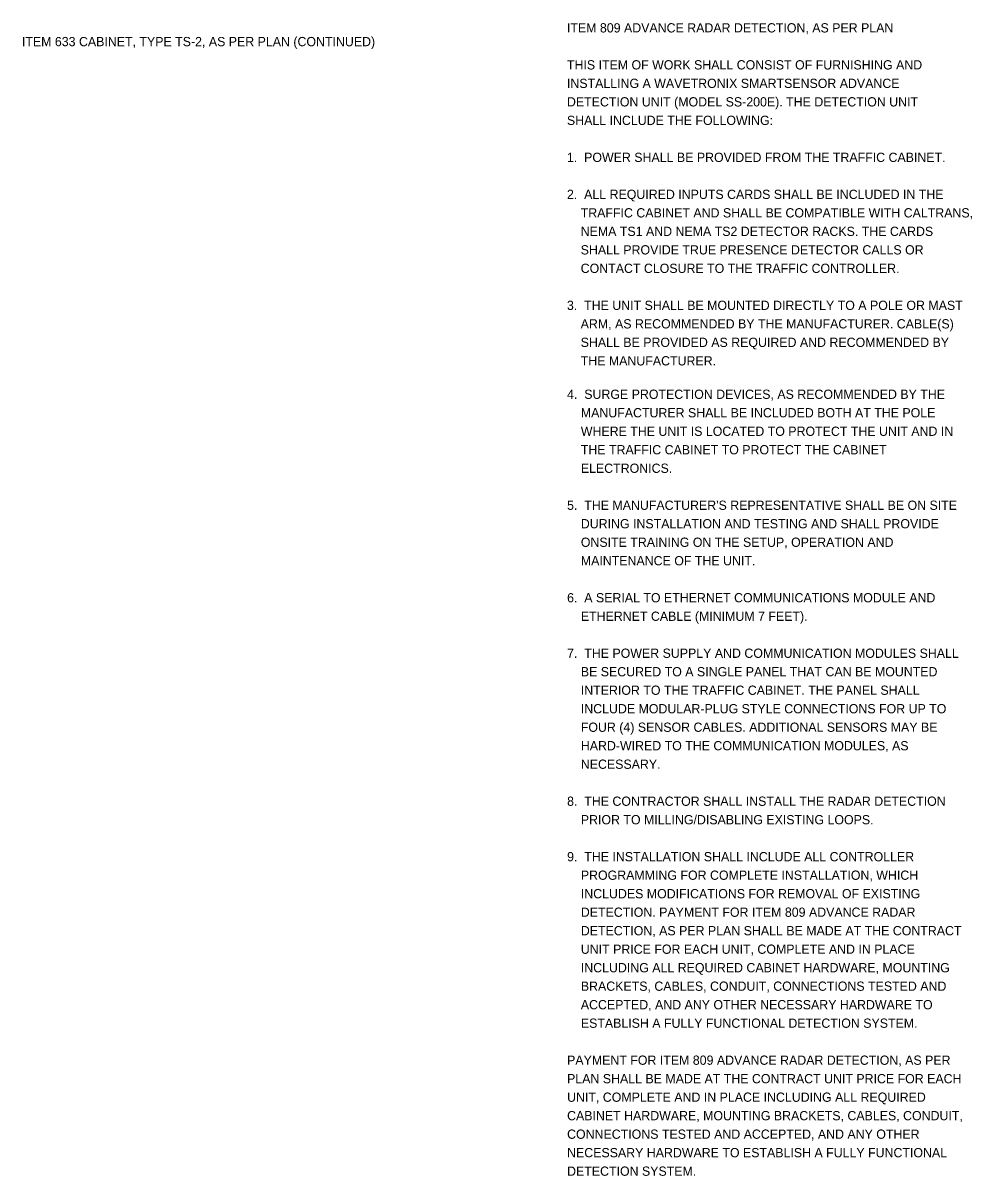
# Model space of a CAD drawing. Extents: x -16 to 109, y -28 to 34.
# Drawn here: x 59.63 to 74, y 3.9 to 21.35 of the extents above; entities that cross this region are included whole.
import ezdxf

# ---------------------------------------------------------------- set-up
doc = ezdxf.new("R2010")
doc.units = 0
doc.layers.add('SH_Text', color=7, linetype='Continuous')

msp = doc.modelspace()

# ---------------------------------------------------------------- texts
at = {"layer": 'SH_Text'}
for s, p in [('ITEM 809 ADVANCE RADAR DETECTION, AS PER PLAN ', (67.868, 21.208)), ('ITEM 633 CABINET, TYPE TS-2, AS PER PLAN (CONTINUED)', (59.617, 21)), ('THIS ITEM OF WORK SHALL CONSIST OF FURNISHING AND', (67.868, 20.648)), ('INSTALLING A WAVETRONIX SMARTSENSOR ADVANCE', (67.868, 20.368)), ('DETECTION UNIT (MODEL SS-200E). THE DETECTION UNIT', (67.868, 20.088)), ('SHALL INCLUDE THE FOLLOWING:', (67.868, 19.808)), ('1.  POWER SHALL BE PROVIDED FROM THE TRAFFIC CABINET.', (67.868, 19.248)), ('2.  ALL REQUIRED INPUTS CARDS SHALL BE INCLUDED IN THE', (67.868, 18.688)), ('    TRAFFIC CABINET AND SHALL BE COMPATIBLE WITH CALTRANS,', (67.868, 18.408)), ('    NEMA TS1 AND NEMA TS2 DETECTOR RACKS. THE CARDS', (67.868, 18.128)), ('    SHALL PROVIDE TRUE PRESENCE DETECTOR CALLS OR', (67.868, 17.848)), ('    CONTACT CLOSURE TO THE TRAFFIC CONTROLLER.', (67.868, 17.568)), ('3.  THE UNIT SHALL BE MOUNTED DIRECTLY TO A POLE OR MAST', (67.868, 17.008)), ('    ARM, AS RECOMMENDED BY THE MANUFACTURER. CABLE(S)', (67.868, 16.728)), ('    SHALL BE PROVIDED AS REQUIRED AND RECOMMENDED BY', (67.868, 16.448)), ('    THE MANUFACTURER.', (67.868, 16.168)), ('4.  SURGE PROTECTION DEVICES, AS RECOMMENDED BY THE', (67.87, 15.662)), ('    MANUFACTURER SHALL BE INCLUDED BOTH AT THE POLE', (67.87, 15.382)), ('    WHERE THE UNIT IS LOCATED TO PROTECT THE UNIT AND IN', (67.87, 15.102)), ('    THE TRAFFIC CABINET TO PROTECT THE CABINET', (67.87, 14.822)), ('    ELECTRONICS.', (67.87, 14.542)), ("5.  THE MANUFACTURER'S REPRESENTATIVE SHALL BE ON SITE", (67.87, 13.982)), ('    DURING INSTALLATION AND TESTING AND SHALL PROVIDE', (67.87, 13.702)), ('    ONSITE TRAINING ON THE SETUP, OPERATION AND', (67.87, 13.422)), ('    MAINTENANCE OF THE UNIT.', (67.87, 13.142)), ('6.  A SERIAL TO ETHERNET COMMUNICATIONS MODULE AND', (67.87, 12.582)), ('    ETHERNET CABLE (MINIMUM 7 FEET).', (67.87, 12.302)), ('7.  THE POWER SUPPLY AND COMMUNICATION MODULES SHALL', (67.87, 11.742)), ('    BE SECURED TO A SINGLE PANEL THAT CAN BE MOUNTED', (67.87, 11.462)), ('    INTERIOR TO THE TRAFFIC CABINET. THE PANEL SHALL', (67.87, 11.182)), ('    INCLUDE MODULAR-PLUG STYLE CONNECTIONS FOR UP TO', (67.87, 10.902)), ('    FOUR (4) SENSOR CABLES. ADDITIONAL SENSORS MAY BE', (67.87, 10.622)), ('    HARD-WIRED TO THE COMMUNICATION MODULES, AS', (67.87, 10.342)), ('    NECESSARY.', (67.87, 10.062)), ('8.  THE CONTRACTOR SHALL INSTALL THE RADAR DETECTION', (67.87, 9.502)), ('    PRIOR TO MILLING/DISABLING EXISTING LOOPS.', (67.87, 9.222)), ('9.  THE INSTALLATION SHALL INCLUDE ALL CONTROLLER', (67.87, 8.662)), ('    PROGRAMMING FOR COMPLETE INSTALLATION, WHICH', (67.87, 8.382)), ('    INCLUDES MODIFICATIONS FOR REMOVAL OF EXISTING', (67.87, 8.102)), ('    DETECTION. PAYMENT FOR ITEM 809 ADVANCE RADAR', (67.87, 7.822)), ('    DETECTION, AS PER PLAN SHALL BE MADE AT THE CONTRACT', (67.87, 7.542)), ('    UNIT PRICE FOR EACH UNIT, COMPLETE AND IN PLACE', (67.87, 7.262)), ('    INCLUDING ALL REQUIRED CABINET HARDWARE, MOUNTING', (67.87, 6.982)), ('    BRACKETS, CABLES, CONDUIT, CONNECTIONS TESTED AND', (67.87, 6.702)), ('    ACCEPTED, AND ANY OTHER NECESSARY HARDWARE TO', (67.87, 6.422)), ('    ESTABLISH A FULLY FUNCTIONAL DETECTION SYSTEM.', (67.87, 6.142)), ('PAYMENT FOR ITEM 809 ADVANCE RADAR DETECTION, AS PER', (67.87, 5.582)), ('PLAN SHALL BE MADE AT THE CONTRACT UNIT PRICE FOR EACH', (67.87, 5.302)), ('UNIT, COMPLETE AND IN PLACE INCLUDING ALL REQUIRED', (67.87, 5.022)), ('CABINET HARDWARE, MOUNTING BRACKETS, CABLES, CONDUIT,', (67.87, 4.742)), ('CONNECTIONS TESTED AND ACCEPTED, AND ANY OTHER', (67.87, 4.462)), ('NECESSARY HARDWARE TO ESTABLISH A FULLY FUNCTIONAL', (67.87, 4.182)), ('DETECTION SYSTEM.', (67.87, 3.902))]:
    msp.add_text(s, height=0.14, dxfattribs=at).set_placement(p)

doc.saveas('drawing.dxf')
